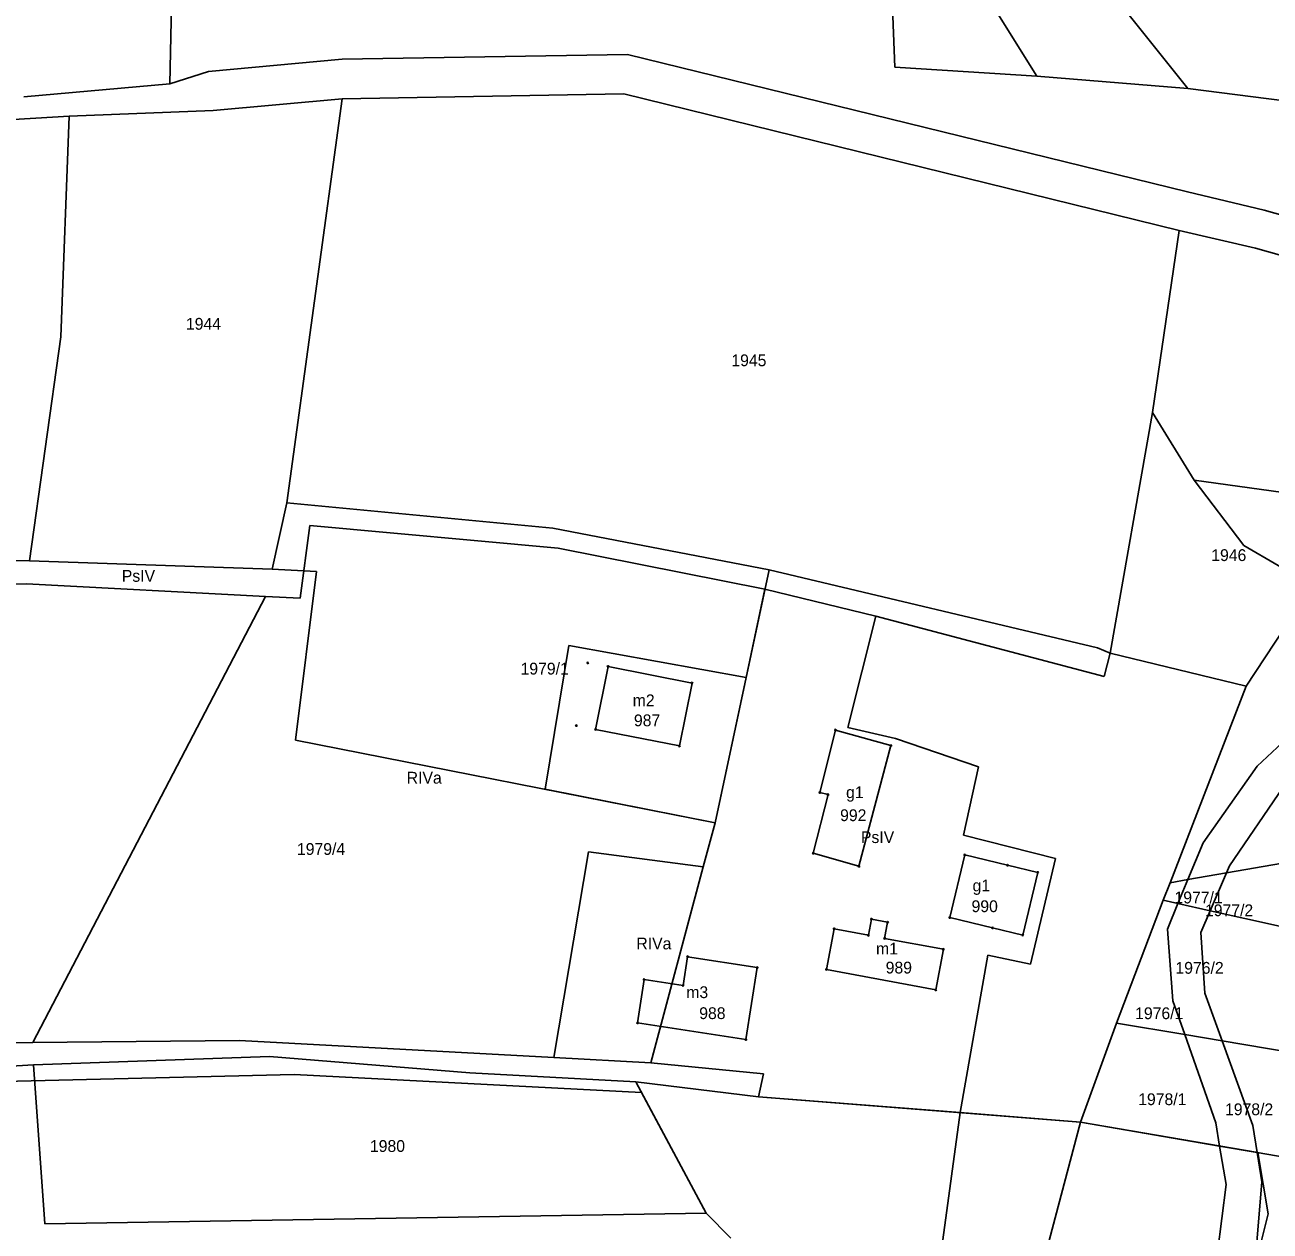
# Model space of a CAD drawing. Extents: x 7498273 to 7499989, y 5499795 to 5500810.
# Drawn here: x 7499038.9 to 7499197.4, y 5500061.4 to 5500214.9 of the extents above; entities that cross this region are included whole.
import ezdxf

# ---------------------------------------------------------------- set-up
doc = ezdxf.new("R2010")
doc.units = 0
for name, color, linetype in [('209-oznaczenie konturu klasyfikacyjnego', 7, 'Continuous'), ('211-numer działki ewidencyjnej', 7, 'Continuous'), ('217-kontur klasyfikacyjny', 7, 'Continuous'), ('218-kontur użytku gruntowego', 7, 'Continuous'), ('219-działka ewidencyjna', 7, 'Continuous'), ('312-budynek ewidencyjny', 7, 'Continuous'), ('312-oznaczenie budynku ewidencyjnego', 7, 'Continuous'), ('312-oznaczenie budynku ewidencyjnego-Atr117', 7, 'Continuous'), ('Punkt budynku', 7, 'Continuous')]:
    doc.layers.add(name, color=color, linetype=linetype)

# ---------------------------------------------------------------- blocks, each defined once
blk = doc.blocks.new('PUNKTBUD')
blk.add_circle((0, 0), 0.09)

msp = doc.modelspace()

# ---------------------------------------------------------------- linework, layer by layer
at = {"layer": '217-kontur klasyfikacyjny'}
for points in [[(7499163.5, 5500236.04), (7499186.88, 5500206.79)], [(7499161.45, 5500218.36), (7499167.66, 5500208.35)], [(7499115.57, 5500211.12), (7499079.27, 5500210.51)], [(7499186.87, 5500193.65), (7499115.57, 5500211.12)], [(7499079.27, 5500210.51), (7499062.26, 5500208.94)], [(7499062.26, 5500208.94), (7499057.33, 5500207.41)], [(7499167.66, 5500208.35), (7499186.88, 5500206.79)], [(7499057.33, 5500207.41), (7499038.75, 5500205.74)], [(7499186.88, 5500206.79), (7499207.52, 5500204.16)], [(7499062.83, 5500204), (7499079.25, 5500205.48)], [(7499079.25, 5500205.48), (7499115.12, 5500206.11)], [(7499115.12, 5500206.11), (7499185.79, 5500188.72)], [(7499014.74, 5500201.49), (7499044.53, 5500203.27)], [(7499044.53, 5500203.27), (7499062.83, 5500204)], [(7499196.63, 5500191.33), (7499186.87, 5500193.65)], [(7499209.3, 5500187.74), (7499196.63, 5500191.33)], [(7499185.79, 5500188.72), (7499182.42, 5500165.58)], [(7499195.49, 5500186.46), (7499185.79, 5500188.72)], [(7499208.43, 5500182.85), (7499195.49, 5500186.46)], [(7499182.42, 5500165.58), (7499177.01, 5500134.96)], [(7499072.21, 5500154.08), (7499070.34, 5500145.64)], [(7499106.08, 5500150.86), (7499072.21, 5500154.08)], [(7499073.93, 5500141.96), (7499075.17, 5500151.2)], [(7499075.17, 5500151.2), (7499106.74, 5500148.31)], [(7499133.6, 5500145.56), (7499106.08, 5500150.86)], [(7499106.74, 5500148.31), (7499133.07, 5500143.09)], [(7499039.49, 5500146.69), (7499011.39, 5500146.84)], [(7499070.34, 5500145.64), (7499039.49, 5500146.69)], [(7499175.42, 5500135.62), (7499133.6, 5500145.56)], [(7498993.23, 5500143.46), (7499039.1, 5500143.76)], [(7499039.1, 5500143.76), (7499069.52, 5500142.16)], [(7499130.67, 5500131.84), (7499133.07, 5500143.09)], [(7499133.07, 5500143.09), (7499147.17, 5500139.65)], [(7499039.89, 5500085.43), (7499069.52, 5500142.16)], [(7499069.52, 5500142.16), (7499073.93, 5500141.96)], [(7499143.63, 5500125.51), (7499147.17, 5500139.65)], [(7499147.17, 5500139.65), (7499176.23, 5500131.98)], [(7499105.12, 5500117.63), (7499108.13, 5500135.94)], [(7499108.13, 5500135.94), (7499130.67, 5500131.84)], [(7499177.01, 5500134.96), (7499175.42, 5500135.62)], [(7499176.23, 5500131.98), (7499177.01, 5500134.96)], [(7499130.67, 5500131.84), (7499126.74, 5500113.38)], [(7499149.71, 5500124.09), (7499143.63, 5500125.51)], [(7499160.24, 5500120.47), (7499149.71, 5500124.09)], [(7499158.35, 5500111.78), (7499160.24, 5500120.47)], [(7499126.74, 5500113.38), (7499105.12, 5500117.63)], [(7499125.23, 5500107.76), (7499126.74, 5500113.38)], [(7499170.05, 5500108.81), (7499158.35, 5500111.78)], [(7499106.19, 5500083.5), (7499110.6, 5500109.68)], [(7499110.6, 5500109.68), (7499125.23, 5500107.76)], [(7499166.88, 5500095.36), (7499170.05, 5500108.81)], [(7499118.53, 5500082.83), (7499125.23, 5500107.76)], [(7499157.9, 5500076.49), (7499161.44, 5500096.54)], [(7499161.44, 5500096.54), (7499166.88, 5500095.36)], [(7499039.89, 5500085.43), (7499030.44, 5500085.3)], [(7499066.18, 5500085.68), (7499039.89, 5500085.43)], [(7499106.19, 5500083.5), (7499066.18, 5500085.68)], [(7499118.53, 5500082.83), (7499106.19, 5500083.5)], [(7499132.88, 5500081.43), (7499118.53, 5500082.83)], [(7499029.08, 5500080.27), (7499073.14, 5500081.34)], [(7499073.14, 5500081.34), (7499117.38, 5500079.06)], [(7499132.27, 5500078.5), (7499132.88, 5500081.43)], [(7499117.38, 5500079.06), (7499125.61, 5500063.7)], [(7499157.9, 5500076.49), (7499132.27, 5500078.5)], [(7499155.71, 5500060.31), (7499157.9, 5500076.49)], [(7499157.9, 5500076.49), (7499173.24, 5500075.29)], [(7499173.24, 5500075.29), (7499190.94, 5500072.24)], [(7499190.94, 5500072.24), (7499195.8, 5500071.4)], [(7499195.8, 5500071.4), (7499197.13, 5500063.62)], [(7499125.61, 5500063.7), (7499128.74, 5500060.51)], [(7499197.13, 5500063.62), (7499194.92, 5500054.79)]]:
    msp.add_lwpolyline(points, dxfattribs=at)
at = {"layer": '218-kontur użytku gruntowego'}
for points in [[(7499163.5, 5500236.04), (7499186.88, 5500206.79)], [(7499161.45, 5500218.36), (7499167.66, 5500208.35)], [(7499115.57, 5500211.12), (7499079.27, 5500210.51)], [(7499186.87, 5500193.65), (7499115.57, 5500211.12)], [(7499079.27, 5500210.51), (7499062.26, 5500208.94)], [(7499062.26, 5500208.94), (7499057.33, 5500207.41)], [(7499167.66, 5500208.35), (7499186.88, 5500206.79)], [(7499057.33, 5500207.41), (7499038.75, 5500205.74)], [(7499186.88, 5500206.79), (7499207.52, 5500204.16)], [(7499062.83, 5500204), (7499079.25, 5500205.48)], [(7499079.25, 5500205.48), (7499115.12, 5500206.11)], [(7499115.12, 5500206.11), (7499185.79, 5500188.72)], [(7499014.74, 5500201.49), (7499044.53, 5500203.27)], [(7499044.53, 5500203.27), (7499062.83, 5500204)], [(7499196.63, 5500191.33), (7499186.87, 5500193.65)], [(7499209.3, 5500187.74), (7499196.63, 5500191.33)], [(7499185.79, 5500188.72), (7499182.42, 5500165.58)], [(7499195.49, 5500186.46), (7499185.79, 5500188.72)], [(7499208.43, 5500182.85), (7499195.49, 5500186.46)], [(7499182.42, 5500165.58), (7499177.01, 5500134.96)], [(7499072.21, 5500154.08), (7499070.34, 5500145.64)], [(7499106.08, 5500150.86), (7499072.21, 5500154.08)], [(7499075.17, 5500151.2), (7499073.93, 5500141.96)], [(7499106.74, 5500148.31), (7499075.17, 5500151.2)], [(7499133.6, 5500145.56), (7499106.08, 5500150.86)], [(7499133.07, 5500143.09), (7499106.74, 5500148.31)], [(7499039.49, 5500146.69), (7499011.39, 5500146.84)], [(7499070.34, 5500145.64), (7499039.49, 5500146.69)], [(7499175.42, 5500135.62), (7499133.6, 5500145.56)], [(7499039.1, 5500143.76), (7498993.23, 5500143.46)], [(7499069.52, 5500142.16), (7499039.1, 5500143.76)], [(7499133.07, 5500143.09), (7499130.67, 5500131.84)], [(7499147.17, 5500139.65), (7499133.07, 5500143.09)], [(7499069.52, 5500142.16), (7499039.89, 5500085.43)], [(7499073.93, 5500141.96), (7499069.52, 5500142.16)], [(7499143.63, 5500125.51), (7499147.17, 5500139.65)], [(7499147.17, 5500139.65), (7499176.23, 5500131.98)], [(7499108.13, 5500135.94), (7499105.12, 5500117.63)], [(7499130.67, 5500131.84), (7499108.13, 5500135.94)], [(7499177.01, 5500134.96), (7499175.42, 5500135.62)], [(7499176.23, 5500131.98), (7499177.01, 5500134.96)], [(7499126.74, 5500113.38), (7499130.67, 5500131.84)], [(7499149.71, 5500124.09), (7499143.63, 5500125.51)], [(7499160.24, 5500120.47), (7499149.71, 5500124.09)], [(7499158.35, 5500111.78), (7499160.24, 5500120.47)], [(7499105.12, 5500117.63), (7499126.74, 5500113.38)], [(7499126.74, 5500113.38), (7499125.23, 5500107.76)], [(7499170.05, 5500108.81), (7499158.35, 5500111.78)], [(7499110.6, 5500109.68), (7499106.19, 5500083.5)], [(7499125.23, 5500107.76), (7499110.6, 5500109.68)], [(7499166.88, 5500095.36), (7499170.05, 5500108.81)], [(7499118.53, 5500082.83), (7499125.23, 5500107.76)], [(7499157.9, 5500076.49), (7499161.44, 5500096.54)], [(7499161.44, 5500096.54), (7499166.88, 5500095.36)], [(7499030.44, 5500085.3), (7499039.89, 5500085.43)], [(7499039.89, 5500085.43), (7499066.18, 5500085.68)], [(7499066.18, 5500085.68), (7499106.19, 5500083.5)], [(7499106.19, 5500083.5), (7499118.53, 5500082.83)], [(7499118.53, 5500082.83), (7499132.88, 5500081.43)], [(7499073.14, 5500081.34), (7499029.08, 5500080.27)], [(7499117.38, 5500079.06), (7499073.14, 5500081.34)], [(7499132.88, 5500081.43), (7499132.27, 5500078.5)], [(7499125.61, 5500063.7), (7499117.38, 5500079.06)], [(7499132.27, 5500078.5), (7499157.9, 5500076.49)], [(7499157.9, 5500076.49), (7499155.71, 5500060.31)], [(7499173.24, 5500075.29), (7499157.9, 5500076.49)], [(7499195.8, 5500071.4), (7499173.24, 5500075.29)], [(7499197.13, 5500063.62), (7499195.8, 5500071.4)], [(7499128.74, 5500060.51), (7499125.61, 5500063.7)], [(7499194.92, 5500054.79), (7499197.13, 5500063.62)]]:
    msp.add_lwpolyline(points, dxfattribs=at)
at = {"layer": '219-działka ewidencyjna'}
for points in [[(7499057.33, 5500207.41), (7499058.18, 5500247.62)], [(7499163.5, 5500236.04), (7499186.88, 5500206.79)], [(7499148.97, 5500225.78), (7499149.62, 5500209.51)], [(7499079.27, 5500210.51), (7499115.57, 5500211.12)], [(7499115.57, 5500211.12), (7499186.87, 5500193.65)], [(7499062.26, 5500208.94), (7499079.27, 5500210.51)], [(7499167.66, 5500208.35), (7499149.62, 5500209.51)], [(7499057.33, 5500207.41), (7499062.26, 5500208.94)], [(7499167.66, 5500208.35), (7499186.88, 5500206.79)], [(7499038.75, 5500205.74), (7499057.33, 5500207.41)], [(7499186.88, 5500206.79), (7499207.52, 5500204.16)], [(7499062.83, 5500204), (7499079.25, 5500205.48)], [(7499072.21, 5500154.08), (7499079.25, 5500205.48)], [(7499079.25, 5500205.48), (7499115.12, 5500206.11)], [(7499185.79, 5500188.72), (7499115.12, 5500206.11)], [(7499014.74, 5500201.49), (7499044.53, 5500203.27)], [(7499043.45, 5500175.19), (7499044.53, 5500203.27)], [(7499044.53, 5500203.27), (7499062.83, 5500204)], [(7499186.87, 5500193.65), (7499196.63, 5500191.33)], [(7499196.63, 5500191.33), (7499209.3, 5500187.74)], [(7499182.42, 5500165.58), (7499185.79, 5500188.72)], [(7499185.79, 5500188.72), (7499195.49, 5500186.46)], [(7499195.49, 5500186.46), (7499208.43, 5500182.85)], [(7499043.45, 5500175.19), (7499039.49, 5500146.69)], [(7499177.01, 5500134.96), (7499182.42, 5500165.58)], [(7499187.72, 5500156.98), (7499182.42, 5500165.58)], [(7499187.72, 5500156.98), (7499194.03, 5500148.64)], [(7499187.72, 5500156.98), (7499215.88, 5500153.04)], [(7499070.34, 5500145.64), (7499072.21, 5500154.08)], [(7499106.08, 5500150.86), (7499072.21, 5500154.08)], [(7499106.08, 5500150.86), (7499133.6, 5500145.56)], [(7499194.03, 5500148.64), (7499202.75, 5500143.55)], [(7499011.39, 5500146.84), (7499039.49, 5500146.69)], [(7499039.49, 5500146.69), (7499070.34, 5500145.64)], [(7499070.34, 5500145.64), (7499076.01, 5500145.36)], [(7499073.34, 5500123.87), (7499076.01, 5500145.36)], [(7499126.74, 5500113.38), (7499133.6, 5500145.56)], [(7499175.42, 5500135.62), (7499133.6, 5500145.56)], [(7499194.32, 5500130.74), (7499202.75, 5500143.55)], [(7499175.42, 5500135.62), (7499177.01, 5500134.96)], [(7499177.01, 5500134.96), (7499194.32, 5500130.74)], [(7499195.73, 5500120.55), (7499208.44, 5500132.43)], [(7499184.63, 5500105.74), (7499194.32, 5500130.74)], [(7499073.34, 5500123.87), (7499126.74, 5500113.38)], [(7499188.83, 5500110.83), (7499195.73, 5500120.55)], [(7499192.18, 5500107.88), (7499199.04, 5500117.9)], [(7499221.56, 5500112.14), (7499191.8, 5500106.98)], [(7499186.9, 5500106.13), (7499188.83, 5500110.83)], [(7499186.9, 5500106.13), (7499191.8, 5500106.98)], [(7499189.74, 5500102.18), (7499191.8, 5500106.98)], [(7499191.8, 5500106.98), (7499192.18, 5500107.88)], [(7499183.76, 5500103.51), (7499184.63, 5500105.74)], [(7499184.63, 5500105.74), (7499186.9, 5500106.13)], [(7499185.64, 5500103.09), (7499186.9, 5500106.13)], [(7499177.81, 5500087.89), (7499183.76, 5500103.51)], [(7499183.76, 5500103.51), (7499185.64, 5500103.09)], [(7499185.64, 5500103.09), (7499184.31, 5500099.85)], [(7499185.64, 5500103.09), (7499189.74, 5500102.18)], [(7499189.74, 5500102.18), (7499188.54, 5500099.39)], [(7499248.99, 5500089.05), (7499189.74, 5500102.18)], [(7499184.31, 5500099.85), (7499185, 5500090.7)], [(7499188.54, 5500099.39), (7499189.08, 5500091.69)], [(7499186.5, 5500086.42), (7499185, 5500090.7)], [(7499191.28, 5500085.61), (7499189.08, 5500091.69)], [(7499173.24, 5500075.29), (7499177.81, 5500087.89)], [(7499177.81, 5500087.89), (7499186.5, 5500086.42)], [(7499186.5, 5500086.42), (7499190.45, 5500075.2)], [(7499186.5, 5500086.42), (7499191.28, 5500085.61)], [(7499241.2, 5500077.18), (7499191.28, 5500085.61)], [(7499191.28, 5500085.61), (7499195.18, 5500074.87)], [(7499026.6, 5500081.75), (7499039.99, 5500082.58)], [(7499070.02, 5500083.65), (7499039.99, 5500082.58)], [(7499039.99, 5500082.58), (7499041.42, 5500062.32)], [(7499070.02, 5500083.65), (7499095.5, 5500081.54)], [(7499095.5, 5500081.54), (7499116.65, 5500080.42)], [(7499116.65, 5500080.42), (7499125.61, 5500063.7)], [(7499116.65, 5500080.42), (7499132.27, 5500078.5)], [(7499132.27, 5500078.5), (7499173.24, 5500075.29)], [(7499169.24, 5500060.21), (7499173.24, 5500075.29)], [(7499173.24, 5500075.29), (7499190.94, 5500072.24)], [(7499190.45, 5500075.2), (7499190.94, 5500072.24)], [(7499195.18, 5500074.87), (7499195.73, 5500071.41)], [(7499190.94, 5500072.24), (7499195.73, 5500071.41)], [(7499190.94, 5500072.24), (7499191.76, 5500067.35)], [(7499195.73, 5500071.41), (7499196.32, 5500067.68)], [(7499228.12, 5500065.83), (7499195.73, 5500071.41)], [(7499190.67, 5500058.68), (7499191.76, 5500067.35)], [(7499195.5, 5500057.99), (7499196.32, 5500067.68)], [(7499041.42, 5500062.32), (7499125.61, 5500063.7)]]:
    msp.add_lwpolyline(points, dxfattribs=at)
at = {"layer": '312-budynek ewidencyjny'}
for points in [[(7499111.52, 5500125.25), (7499113.1, 5500133.26)], [(7499113.1, 5500133.26), (7499123.79, 5500131.15)], [(7499123.79, 5500131.15), (7499122.19, 5500123.14)], [(7499122.19, 5500123.14), (7499111.52, 5500125.25)], [(7499140.06, 5500117.22), (7499142.05, 5500125.17)], [(7499142.05, 5500125.17), (7499149.1, 5500123.19)], [(7499149.1, 5500123.19), (7499145.04, 5500107.83)], [(7499139.23, 5500109.5), (7499141.1, 5500116.96)], [(7499141.1, 5500116.96), (7499140.06, 5500117.22)], [(7499145.04, 5500107.83), (7499139.23, 5500109.5)], [(7499156.59, 5500101.31), (7499158.51, 5500109.28)], [(7499158.51, 5500109.28), (7499163.95, 5500107.97)], [(7499163.95, 5500107.97), (7499167.79, 5500107.05)], [(7499167.79, 5500107.05), (7499165.88, 5500099.08)], [(7499146.24, 5500099.05), (7499146.63, 5500101.11)], [(7499146.63, 5500101.11), (7499148.69, 5500100.72)], [(7499148.69, 5500100.72), (7499148.31, 5500098.66)], [(7499162.05, 5500100), (7499156.59, 5500101.31)], [(7499165.88, 5500099.08), (7499162.05, 5500100)], [(7499140.9, 5500094.71), (7499141.87, 5500099.88)], [(7499141.87, 5500099.88), (7499146.24, 5500099.05)], [(7499148.31, 5500098.66), (7499155.78, 5500097.27)], [(7499155.78, 5500097.27), (7499154.81, 5500092.1)], [(7499122.65, 5500092.67), (7499123.22, 5500096.33)], [(7499123.22, 5500096.33), (7499132.09, 5500094.94)], [(7499132.09, 5500094.94), (7499130.65, 5500085.78)], [(7499154.81, 5500092.1), (7499140.9, 5500094.71)], [(7499116.87, 5500087.91), (7499117.7, 5500093.41)], [(7499117.7, 5500093.41), (7499122.65, 5500092.67)], [(7499130.65, 5500085.78), (7499116.87, 5500087.91)]]:
    msp.add_lwpolyline(points, dxfattribs=at)

# ---------------------------------------------------------------- block references
at = {"layer": 'Punkt budynku'}
for p in [(7499110.52, 5500133.71), (7499113.1, 5500133.26), (7499123.79, 5500131.15), (7499109.07, 5500125.73), (7499111.52, 5500125.25), (7499142.05, 5500125.17), (7499122.19, 5500123.14), (7499149.1, 5500123.19), (7499140.06, 5500117.22), (7499141.1, 5500116.96), (7499139.23, 5500109.5), (7499145.04, 5500107.83), (7499158.51, 5500109.28), (7499163.95, 5500107.97), (7499167.79, 5500107.05), (7499141.87, 5500099.88), (7499146.63, 5500101.11), (7499148.69, 5500100.72), (7499156.59, 5500101.31), (7499162.05, 5500100), (7499146.24, 5500099.05), (7499148.31, 5500098.66), (7499165.88, 5500099.08), (7499155.78, 5500097.27), (7499123.22, 5500096.33), (7499132.09, 5500094.94), (7499140.9, 5500094.71), (7499117.7, 5500093.41), (7499122.65, 5500092.67), (7499154.81, 5500092.1), (7499116.87, 5500087.91), (7499130.65, 5500085.78)]:
    msp.add_blockref('PUNKTBUD', p, dxfattribs=at)

# ---------------------------------------------------------------- texts
at = {"layer": '209-oznaczenie konturu klasyfikacyjnego'}
for s, p in [('PsIV', (7499051.22, 5500144.03)), ('RIVa', (7499087.48, 5500118.35)), ('PsIV', (7499145.29, 5500110.79)), ('RIVa', (7499116.71, 5500097.26))]:
    msp.add_text(s, height=1.5, dxfattribs=at).set_placement(p)
at = {"layer": '211-numer działki ewidencyjnej'}
for s, p in [('1944', (7499059.38, 5500176.1)), ('1945', (7499128.8, 5500171.46)), ('1946', (7499189.88, 5500146.67)), ('1979/1', (7499101.97, 5500132.23)), ('1979/4', (7499073.51, 5500109.28)), ('1977/1', (7499185.2, 5500103.11)), ('1977/2', (7499189.08, 5500101.48)), ('1976/2', (7499185.32, 5500094.16)), ('1976/1', (7499180.19, 5500088.38)), ('1978/1', (7499180.58, 5500077.44)), ('1978/2', (7499191.63, 5500076.16)), ('1980', (7499082.8, 5500071.49))]:
    msp.add_text(s, height=1.5, dxfattribs=at).set_placement(p)
at = {"layer": '312-oznaczenie budynku ewidencyjnego'}
for s, p in [('987', (7499116.4, 5500125.65)), ('992', (7499142.64, 5500113.58)), ('990', (7499159.37, 5500102)), ('989', (7499148.44, 5500094.19)), ('988', (7499124.71, 5500088.39))]:
    msp.add_text(s, height=1.5, dxfattribs=at).set_placement(p)
at = {"layer": '312-oznaczenie budynku ewidencyjnego-Atr117'}
for s, p in [('m2', (7499116.246, 5500128.2)), ('g1', (7499143.399, 5500116.5)), ('g1', (7499159.499, 5500104.64)), ('m1', (7499147.215, 5500096.61)), ('m3', (7499123.066, 5500091.06))]:
    msp.add_text(s, height=1.5, dxfattribs=at).set_placement(p)

doc.saveas('drawing.dxf')
